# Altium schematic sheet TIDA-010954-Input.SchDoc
size 431 x 279 mm; Date: Not shown in title block; ApprovedBy: Not shown in title block; CheckedBy: Not shown in title block; Author: Not shown in title block; CompanyName: Not shown in title block; Engineer: Not shown in title block; Organization: Not shown in title block; Address1: Not shown in title block; Address2: Not shown in title block; Address3: Not shown in title block; Address4: Not shown in title block; DocumentNumber: 2; Revision: Use project parameter SCH_Rev; SheetNumber: 5; SheetTotal: 9; PageSetup: Record=PageOptions¦CenterHorizontal=True¦CenterVertical=True¦PrintScale=1.00¦XCorrection=1.00¦YCorrection=1.00¦PrintKind=0¦BorderSize=5000000¦LeftOffset=0¦BottomOffset=0¦Orientation=2¦PaperLength=1000¦PaperWidth=1000¦Scale=100¦PaperSource=15¦PrintQuality=600¦MediaType=1¦DitherType=10¦PaperKind=Letter¦PrintScaleMode=1
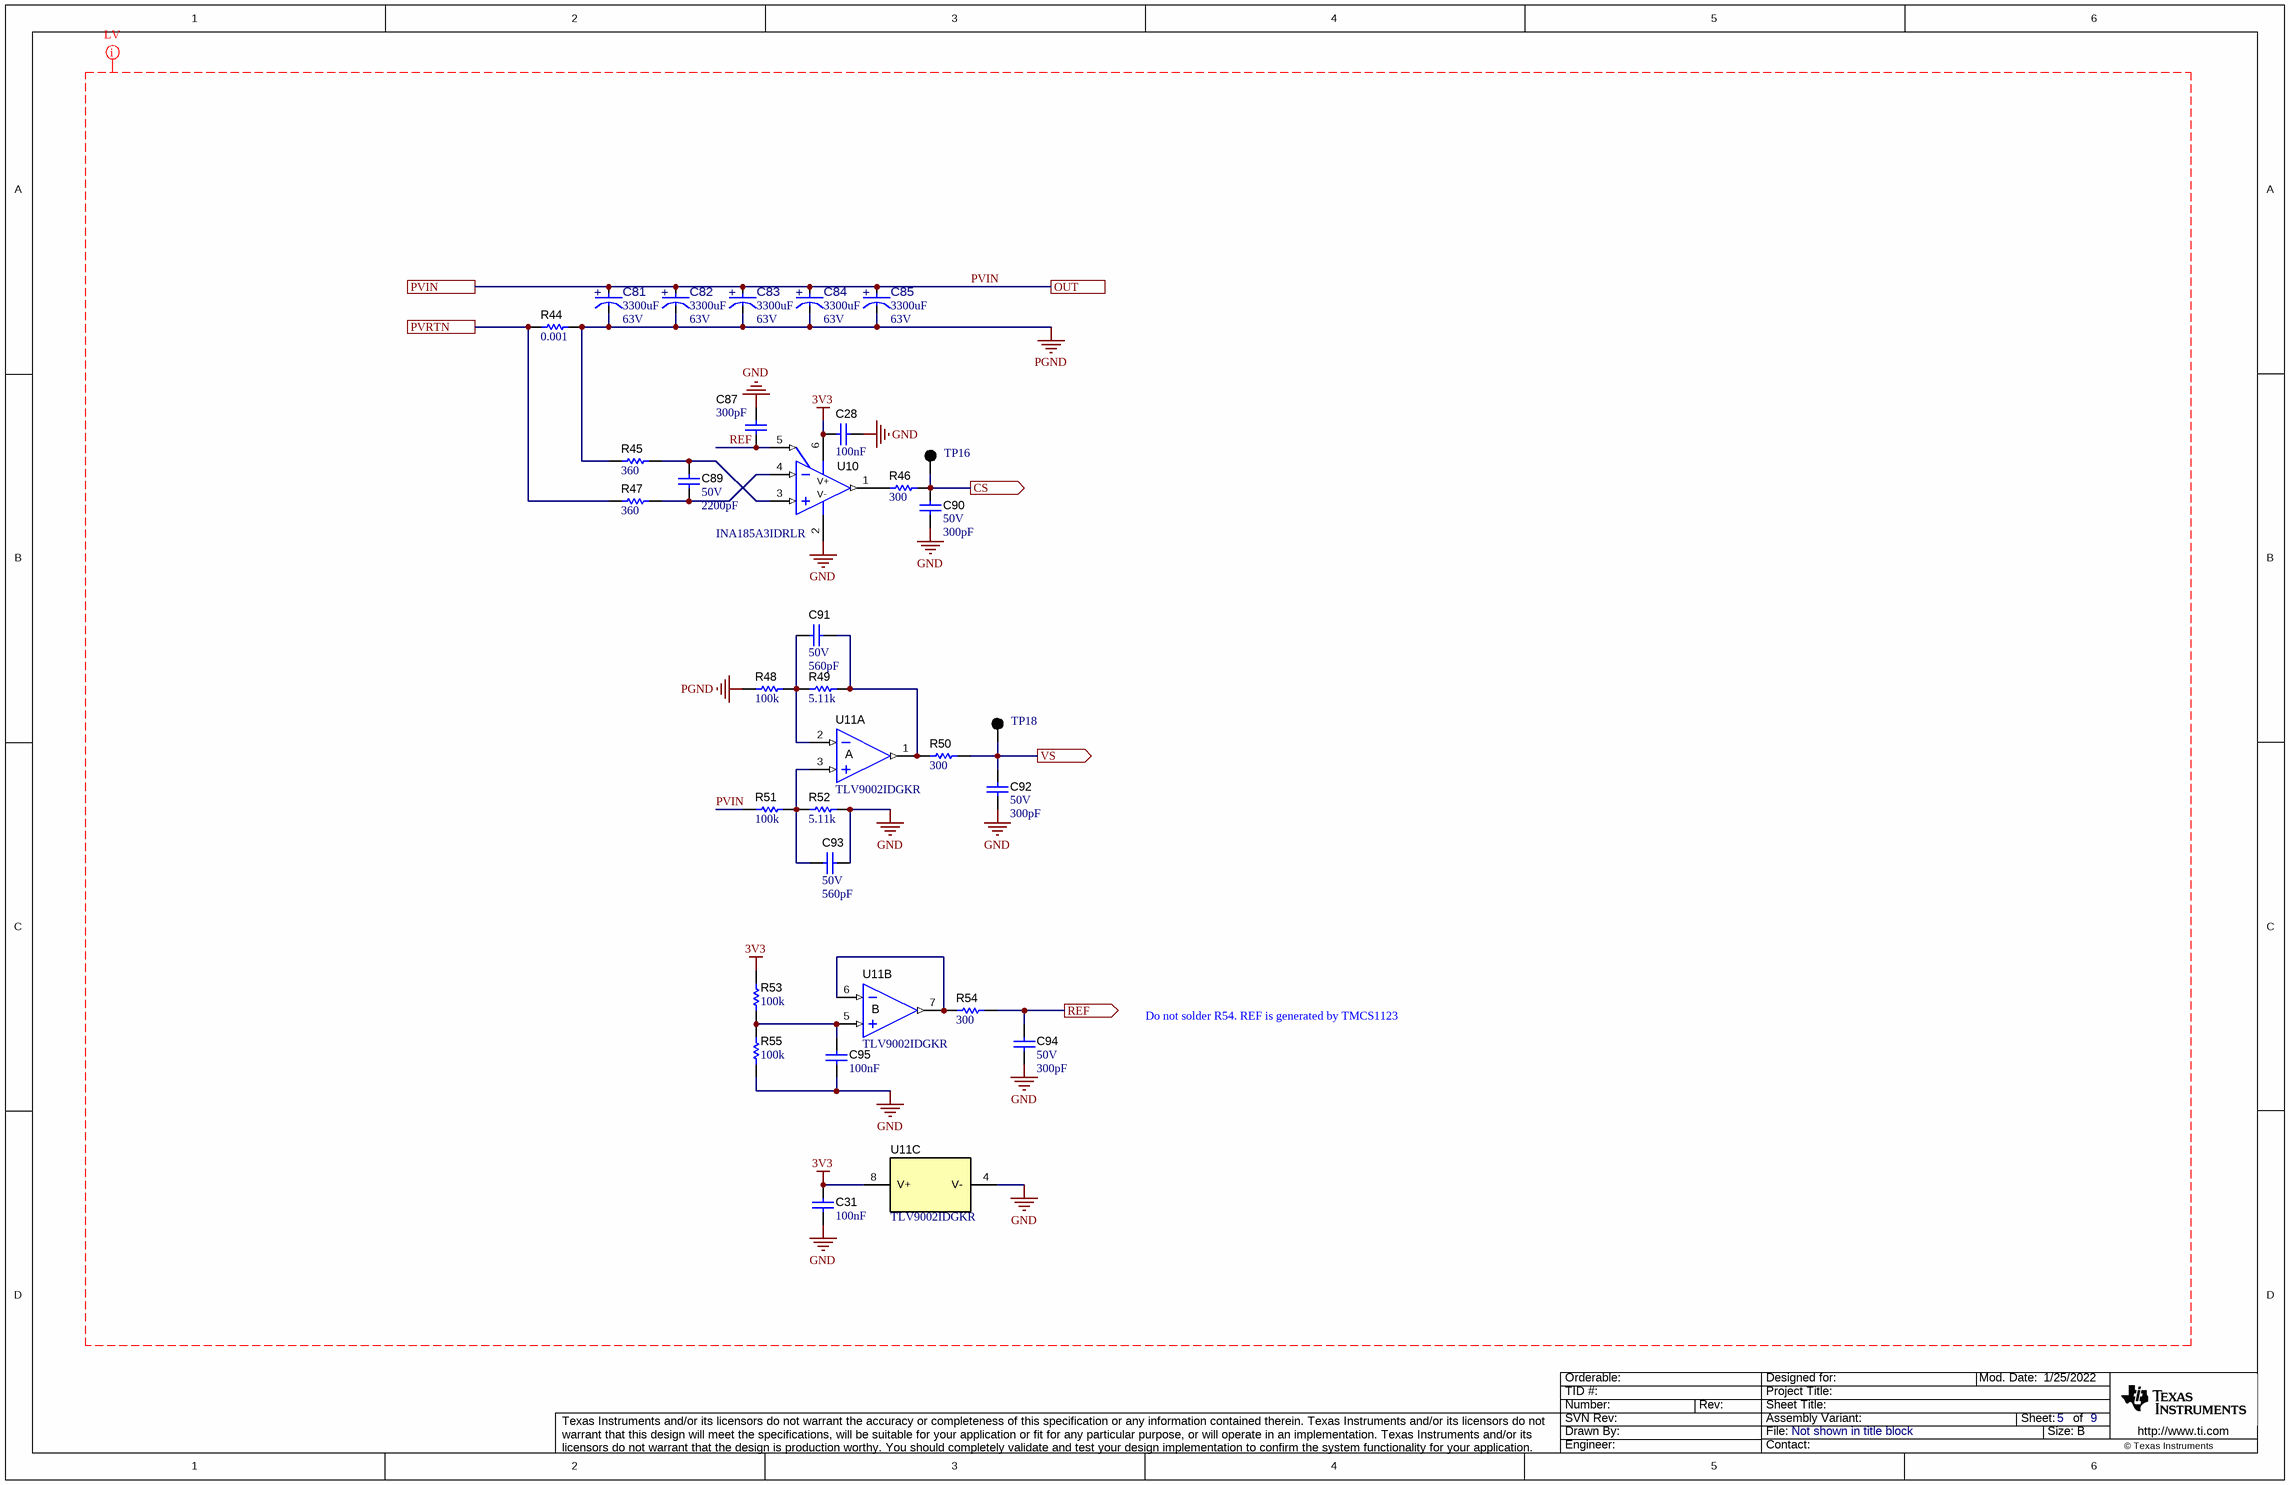
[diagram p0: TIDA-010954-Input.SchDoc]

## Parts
C28  Cap_F: 100nF  [0603]  (hidden comment: CGA3E2X7R1E104K080AA)
C31  Cap_F: 100nF  [0603]  (hidden comment: CGA3E2X7R1E104K080AA)
C81  ValueDisplayed: 3300uF  VDC_V: 63V  [FP-63ZLJ2700M18X40_RADIAL-MFG]  (hidden comment: 63ZLJ2700M18X40)
C82  ValueDisplayed: 3300uF  VDC_V: 63V  [FP-63ZLJ2700M18X40_RADIAL-MFG]  (hidden comment: 63ZLJ2700M18X40)
C83  ValueDisplayed: 3300uF  VDC_V: 63V  [FP-63ZLJ2700M18X40_RADIAL-MFG]  (hidden comment: 63ZLJ2700M18X40)
C84  ValueDisplayed: 3300uF  VDC_V: 63V  [FP-63ZLJ2700M18X40_RADIAL-MFG]  (hidden comment: 63ZLJ2700M18X40)
C85  ValueDisplayed: 3300uF  VDC_V: 63V  [FP-63ZLJ2700M18X40_RADIAL-MFG]  (hidden comment: 63ZLJ2700M18X40)
C87  ValueDisplayed: 300pF  [0603]  (hidden comment: GRM1885C1H301JA01D)
C89  VDC_V: 50V  ValueDisplayed: 2200pF  [0603]  (hidden comment: GRM1885C1H222JA01D)
C90  VDC_V: 50V  ValueDisplayed: 300pF  [0603]  (hidden comment: GRM1885C1H301JA01D)
C91  VDC_V: 50V  ValueDisplayed: 560pF  [0603]  (hidden comment: GRM1885C1H561JA01D)
C92  VDC_V: 50V  ValueDisplayed: 300pF  [0603]  (hidden comment: GRM1885C1H301JA01D)
C93  VDC_V: 50V  ValueDisplayed: 560pF  [0603]  (hidden comment: GRM1885C1H561JA01D)
C94  VDC_V: 50V  ValueDisplayed: 300pF  [0603]  (hidden comment: GRM1885C1H301JA01D)
C95  Cap_F: 100nF  [0603]  (hidden comment: CGA3E2X7R1E104K080AA)
R44  ValueDisplayed: 0.001  [1206]  (hidden comment: CRF1206-FZ-R001ELF)
R45  ValueDisplayed: 360  [0603]  (hidden comment: RC0603JR-07360RL)
R46  ValueDisplayed: 300  [0603]  (hidden comment: RC0603FR-07300RL)
R47  ValueDisplayed: 360  [0603]  (hidden comment: RC0603JR-07360RL)
R48  ValueDisplayed: 100k  [0603]  (hidden comment: RT0603BRD07100KL)
R49  ValueDisplayed: 5.11k  [0603]  (hidden comment: RT0603BRD075K11L)
R50  ValueDisplayed: 300  [0603]  (hidden comment: RC0603FR-07300RL)
R51  ValueDisplayed: 100k  [0805_HV]  (hidden comment: RT0805BRD07100KL)
R52  ValueDisplayed: 5.11k  [0603]  (hidden comment: RT0603BRD075K11L)
R53  ValueDisplayed: 100k  [0603]  (hidden comment: RT0603BRD07100KL)
R54  ValueDisplayed: 300  [0603]  (hidden comment: RC0603FR-07300RL)
R55  ValueDisplayed: 100k  [0603]  (hidden comment: RT0603BRD07100KL)
TP16  5011  [Keystone5011]  (value not drawn)
TP18  5011  [Keystone5011]  (value not drawn)
U10  INA185A3IDRLR  [DRL0006A]
U11  TLV9002IDGKR  [DGK0008A_N]  (parts A,B,C of 3)

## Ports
CS (out), OUT, PVIN, PVRTN, REF (out), VS (out)

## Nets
3V3: C28.1 C31.2 R53.1 U10.6(V+) U11.8(V+)
GND: C28.2 C31.1 C87.2 C90.2 C92.2 C93.1 C94.2 C95.1 R52.2 R55.2 U10.2(V-) U11.4(V-)
PGND: C81.1(CATHODE) C82.1(CATHODE) C83.1(CATHODE) C84.1(CATHODE) C85.1(CATHODE) R44.2 R45.1 R48.1
CS: C90.1 R46.1 TP16.1 ; port CS
PVIN: C81.2(ANODE) C82.2(ANODE) C83.2(ANODE) C84.2(ANODE) C85.2(ANODE) R51.1 ; port PVIN, port OUT
PVRTN: R44.1 R47.1 ; port PVRTN
REF: C94.1 R54.1 ; port REF
REF: C87.1 U10.5(REF)  [a separate net that carries the same name]
VS: C92.1 R50.1 TP18.1 ; port VS
NetC89_1: C89.1 R45.2 U10.3(IN+)
NetC89_2: C89.2 R47.2 U10.4(IN-)
NetC91_1: C91.1 R49.2 R50.2 U11.1(OUT)
NetC91_2: C91.2 R48.2 R49.1 U11.2(IN-)
NetC93_2: C93.2 R51.2 R52.1 U11.3(IN+)
NetC95_2: C95.2 R53.2 R55.1 U11.5(IN+)
NetR46_2: R46.2 U10.1(OUT)
NetR54_2: R54.2 U11.6(IN-) U11.7(OUT)

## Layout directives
net class LV: 3V3, GND, PGND, PVIN, REF

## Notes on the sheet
- Do not solder R54. REF is generated by TMCS1123

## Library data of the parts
C28 C31 C95 = CMP-0007077-5: CAP, CERM, 0.1 uF, 25 V, +/- 10%, X7R, AEC-Q200 Grade 1, 0603; Manufacturer: TDK; TaMin_C: -55°C; Polarized: N; SizeAreaWB_mm2: 4.68; Value1: Unknown; U/M: EA; Value: 0.1uF; TaMax_C: 125°C; SizeZ_mm: 1; SizeX_mm: 1.6; SizeY_mm: 0.8; Value2: 25V; SizeArea_mm2: 1.28; AEC Qualified: Y; AEC Category: Q200
C81-C85 = CMP-0122849-1: 2700 µF 63 V Aluminum Electrolytic Capacitors Radial, Can 10000 Hrs @ 105°C; Manufacturer: Rubycon; Part Number: 63PK3300MEFC18X40; AEC Qualified: No; Cap_F: 2.7mF; IRMS_A: 4.3A; SizeZ_mm: 42mm; Tolerance_%: 20%; Dissipation Factor: 9%; Leakage Current: 1701uA; Life: 10000Hours; Value: 2.7mF
C87 = CMP-0007206-4: CAP, CERM, 300 pF, 50 V, +/- 5%, C0G/NP0, 0603; Manufacturer: MuRata; TaMin_C: -55°C; Polarized: N; SizeAreaWB_mm2: 4.68; Value1: Unknown; U/M: EA; Value: 300pF; TaMax_C: 125°C; SizeZ_mm: 1; SizeX_mm: 1.6; SizeY_mm: 0.8; Value2: 50V; SizeArea_mm2: 1.28; AEC Category: Q200
C89 = CMP-0007198-4: CAP, CERM, 2200 pF, 50 V, +/- 5%, C0G/NP0, 0603; Manufacturer: MuRata; TaMin_C: -55°C; Polarized: N; SizeAreaWB_mm2: 4.68; Value1: Unknown; U/M: EA; Value: 2200pF; TaMax_C: 125°C; SizeZ_mm: 1; SizeX_mm: 1.6; SizeY_mm: 0.8; SizeArea_mm2: 1.28; Cap_F: 2.2nF; AEC Category: Q200
C90 C92 C94 = CMP-0007206-4: CAP, CERM, 300 pF, 50 V, +/- 5%, C0G/NP0, 0603; Manufacturer: MuRata; TaMin_C: -55°C; Polarized: N; SizeAreaWB_mm2: 4.68; Value1: Unknown; U/M: EA; Value: 300pF; TaMax_C: 125°C; SizeZ_mm: 1; SizeX_mm: 1.6; SizeY_mm: 0.8; SizeArea_mm2: 1.28; AEC Category: Q200
C91 C93 = CMP-0007225-4: CAP, CERM, 560 pF, 50 V, +/- 5%, C0G/NP0, 0603; Manufacturer: MuRata; TaMin_C: -55°C; Polarized: N; SizeAreaWB_mm2: 4.68; Value1: Unknown; U/M: EA; Value: 560pF; TaMax_C: 125°C; SizeZ_mm: 1; SizeX_mm: 1.6; SizeY_mm: 0.8; SizeArea_mm2: 1.28; AEC Category: Q200
R44 = CMP-0078821-1: RES, 0.001, 1%, 1 W, AEC-Q200 Grade 0, 1206; Manufacturer: Bourns; Value_Code: 1L000; SizeArea_mm2: 5.12; AEC Qualified: Y; AEC Category: Q200; Res_ohm: 1m; Value: 0.001; SizeZ_mm: 1.35; EIA_Code: E96; TempCo: 50 ppm/C; AEC Grade: 0; SizeY_mm: 1.6; Power_W: 1W; SizeX_mm: 3.2
R45 R47 = CMP-0025914-5: RES, 360, 5%, 0.1 W, 0603; Manufacturer: Yageo; Power_W: 100mW; TempCo: 100 ppm/C; Value_Code: 360R; Value: 360; EIA_Code: E24; SizeX_mm: 1.6; SizeY_mm: 0.8; SizeZ_mm: 1; Value2: 0.1W; SizeArea_mm2: 1.28; AEC Qualified: N; VDC_V: 75V; AEC Category: Q200; SizeAreaWB_mm2: 4.68
R46 R50 R54 = CMP-0023013-5: RES, 300, 1%, 0.1 W, 0603; Manufacturer: Yageo; Power_W: 100mW; TempCo: 100 ppm/C; Value_Code: 300R; Value: 300; SizeX_mm: 1.6; SizeY_mm: 0.8; SizeZ_mm: 1; Value2: 0.1W; SizeArea_mm2: 1.28; AEC Qualified: N; VDC_V: 75V; AEC Category: Q200; SizeAreaWB_mm2: 4.68
R48 R53 R55 = CMP-0023630-3: RES, 100 k, 0.1%, 0.1 W, 0603; Manufacturer: Yageo America; Power_W: 100mW; TempCo: 25 ppm/C; U/M: EA; Value: 100k; EIA_Code: E192; SizeX_mm: 1.6; SizeY_mm: 0.8; SizeZ_mm: 1; Value2: 0.1W; SizeArea_mm2: 1.28; VDC_V: 75V; AEC Category: Q200
R49 R52 = CMP-0024366-2: RES, 5.11 k, 0.1%, 0.1 W, 0603; Manufacturer: Yageo America; Power_W: 100mW; TempCo: 25 ppm/C; Value_Code: 5k11; U/M: EA; Value: 5.11k; EIA_Code: E192; SizeX_mm: 1.6; SizeY_mm: 0.8; SizeZ_mm: 1; Value2: 0.1W; SizeArea_mm2: 1.28; VDC_V: 75V; AEC Category: Q200
R51 = CMP-0019441-2: RES, 100 k, 0.1%, 0.125 W, 0805; Manufacturer: Yageo America; Power_W: 125mW; TempCo: 25 ppm/C; U/M: EA; Value: 100k; EIA_Code: E192; SizeX_mm: 2; SizeY_mm: 1.25; SizeZ_mm: 1.45; Value2: 0.125W; SizeArea_mm2: 2.5; VDC_V: 150V; AEC Category: Q200
TP16 TP18 = CMP-0055148-2: Test Point, Multipurpose, Black, TH; Manufacturer: Keystone Electronics; CNHeader: FALSE; ContactFinish: Silver; Green_REACh: Passed; Green_Lifecycle: Active; CT: TRUE
U10 = CMP-0085240-1: Bidirectional, Precision Low- and High-Side Voltage Output, Current-Sense Amplifier, DRL0006A (SOT-5X3-6); Alternate Manufacturer: Texas Instruments; Alternate PartNumber: INA185A3IDRLT; SizeAreaWB_mm2: 6.76; SizeY_mm: 1.6; CompType: IC; SizeZ_mm: 0.6; AEC Category: Q200; SizeArea_mm2: 2.56; AEC Qualified: N
U11 = CMP-0073533-3: Alternate PartNumber: TLV2333IDGKT; Alternate Manufacturer: Texas Instruments; SizeAreaWB_mm2: 23.6; SizeZ_mm: 1.1; SizeX_mm: 4.9; SizeY_mm: 3; SizeArea_mm2: 14.7; CompType: IC; AEC Category: Q200; AEC Qualified: N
